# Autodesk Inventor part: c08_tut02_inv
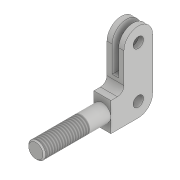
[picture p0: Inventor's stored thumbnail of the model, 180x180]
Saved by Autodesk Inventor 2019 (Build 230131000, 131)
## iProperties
Created: 2015-03
Part Number: c08_tut02_inv
Material: Generic
Document SubType Name: Modeling
Designer: Sandeep
Density: 1 g/cm^3
Appearance: Default
Author: Sandeep
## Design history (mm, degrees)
sketch "Sketch1"
  geometry: L1 (0, 0)-(0, 22); L2 (0, 22)-(5, 22); L3 (10, 27)-(10, 50); L4 (32, 50)-(32, 11); L5 (21, 0)-(0, 0); A1 r 11 centre (21, 50) between (32, 50) and (10, 50); A2 r 11 centre (21, 11) between (21, 0) and (32, 11); A3 r 5 centre (5, 27) between (5, 22) and (10, 27)
  constraints: 10 end point, 6 point on circle, 6 tangent, 3 centre point, 3 perpendicular, 1 parallel, 1 vertical
  dimensions: "d0" = 11 radius of A1; "d1" = 11 radius of A2; "d2" = 5 radius of A3; "d3" = 32 distance between parallel lines of L1 L4; "d4" = 22 distance between parallel lines of L5 L2; "d5" = 50 distance from line of A1.centre L5
extrude "Extrusion1" new body sketch "Sketch1" stored distance "d6" = 13; taper "d7" = 0 deg
hole "Hole1" diameter "d10" = 8; stored, may be unused: countersink angle "d14" = 90 deg, drill point angle "d16" = 118 deg; dims "d8" = 10, "d9" = 10, "d11" = 6, "d12" = 4, "d13" = 2, "d15" = 8
hole "Hole2" diameter "d19" = 8; stored, may be unused: countersink angle "d23" = 90 deg, drill point angle "d25" = 118 deg; dims "d17" = 10, "d18" = 10, "d20" = 6, "d21" = 4, "d22" = 2, "d24" = 8
sketch "Sketch2"
  geometry: L1 (0, -11)-(13, -11) reference; L2 (4, -11)-(4, 20); L3 (4, 20)-(9, 20); L4 (9, 20)-(9, -11); L5 (6.5, 50)-(6.5, -21.602); L6 (13, 50)-(0, 50) reference; L7 (9, -11)-(4, -11)
  constraints: 10 end point, 2 perpendicular, 2 point on line, 2 vertical, 1 collinear, 1 other
  dimensions: "d26" = 5 distance between parallel lines of L4 L2; "d27" = 30 distance between parallel lines of L6 L3
extrude "Extrusion2" cut sketch "Sketch2" extent not by distance; stored distance "d28" = 13; taper "d29" = 0 deg
sketch "Sketch3"
  geometry: L1 (13, 0)-(0, 0) reference; L2 (6.5, 0)-(6.5, 35.061); C1 r 6.5 at (6.5, 11)
  constraints: 2 end point, 1 centre point, 1 point on line, 1 vertical
  dimensions: "d30" = 13 diameter of C1; "d31" = 11 distance from line of C1.centre L1
extrude "Extrusion3" join sketch "Sketch3" distance "d32" = 51; taper "d33" = 0 deg
chamfer "Chamfer1" distance "d34" = 1; stored, may be unused: second distance "d35" = 2, angle "d36" = 45 deg
thread "Thread1" dims "d37" = 34, "d38" = 0
body "Solid1"
